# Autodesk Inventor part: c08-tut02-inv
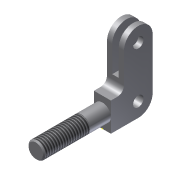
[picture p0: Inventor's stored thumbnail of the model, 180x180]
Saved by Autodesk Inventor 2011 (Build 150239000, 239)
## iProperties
Created: 2010-03
Part Number: c08-tut02-inv
Document SubType Name: Modeling
Designer: CADSoft
Density: 1 g/cm^3
Author: CADSoft
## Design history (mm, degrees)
sketch "Sketch1"
  geometry: 1 further point
sketch "Sketch2"
  geometry: L1 (0, 22)-(0, 0); L2 (0, 0)-(21, 0); L3 (32, 11)-(32, 50); L4 (10, 50)-(10, 27); L5 (5, 22)-(0, 22); C1 r 4 at (21, 50); C2 r 4 at (21, 11); A1 r 11 centre (21, 50) between (32, 50) and (10, 50); A2 r 11 centre (21, 11) between (21, 0) and (32, 11); A3 r 5 centre (5, 27) between (5, 22) and (10, 27); 1 further point
  constraints: 10 end point, 6 point on circle, 6 tangent, 5 centre point, 3 parallel, 2 coincident, 2 point on line, 1 equal radius, 1 perpendicular, 1 vertical
  dimensions: "d0" = 22 distance of L1.start L1.end; "d1" = 32 distance of L1.end point (32, 0); "d2" = 11 radius of A2; "d3" = 50 distance from line of A1.centre L2; "d4" = 11 radius of A1; "d5" = 5 radius of A3; "d6" = 8 diameter of C1
extrude "Extrusion1" new body sketch "Sketch2" stored distance "d7" = 13; taper "d8" = 0 deg
sketch "Sketch4"
  geometry: L1 (9, -19)-(4, -19); L2 (4, -19)-(4, -50); L3 (4, -50)-(9, -50); L4 (9, -50)-(9, -19); L5 (0, -50)-(0, -39) reference; 1 further point
  constraints: 8 end point, 2 parallel, 1 horizontal, 1 perpendicular, 1 point on line
  dimensions: "d12" = 5 distance of L2.end L3.end; "d15" = 30 distance from line of L1 point (6.5, 11)
extrude "Extrusion3" cut sketch "Sketch4" stored distance "d16" = 5; taper "d17" = 0 deg
sketch "Sketch5"
  geometry: C1 r 6.5 at (6.5, -11); 1 further point
  constraints: 1 centre point
  dimensions: "d18" = 13 diameter of C1
extrude "Extrusion4" join sketch "Sketch5" distance "d19" = 51; taper "d20" = 0 deg
chamfer "Chamfer1" distance "d21" = 1; stored, may be unused: second distance "d22" = 2, angle "d23" = 45 deg
thread "Thread1" dims "d24" = 34, "d25" = 0
body "Solid1"
